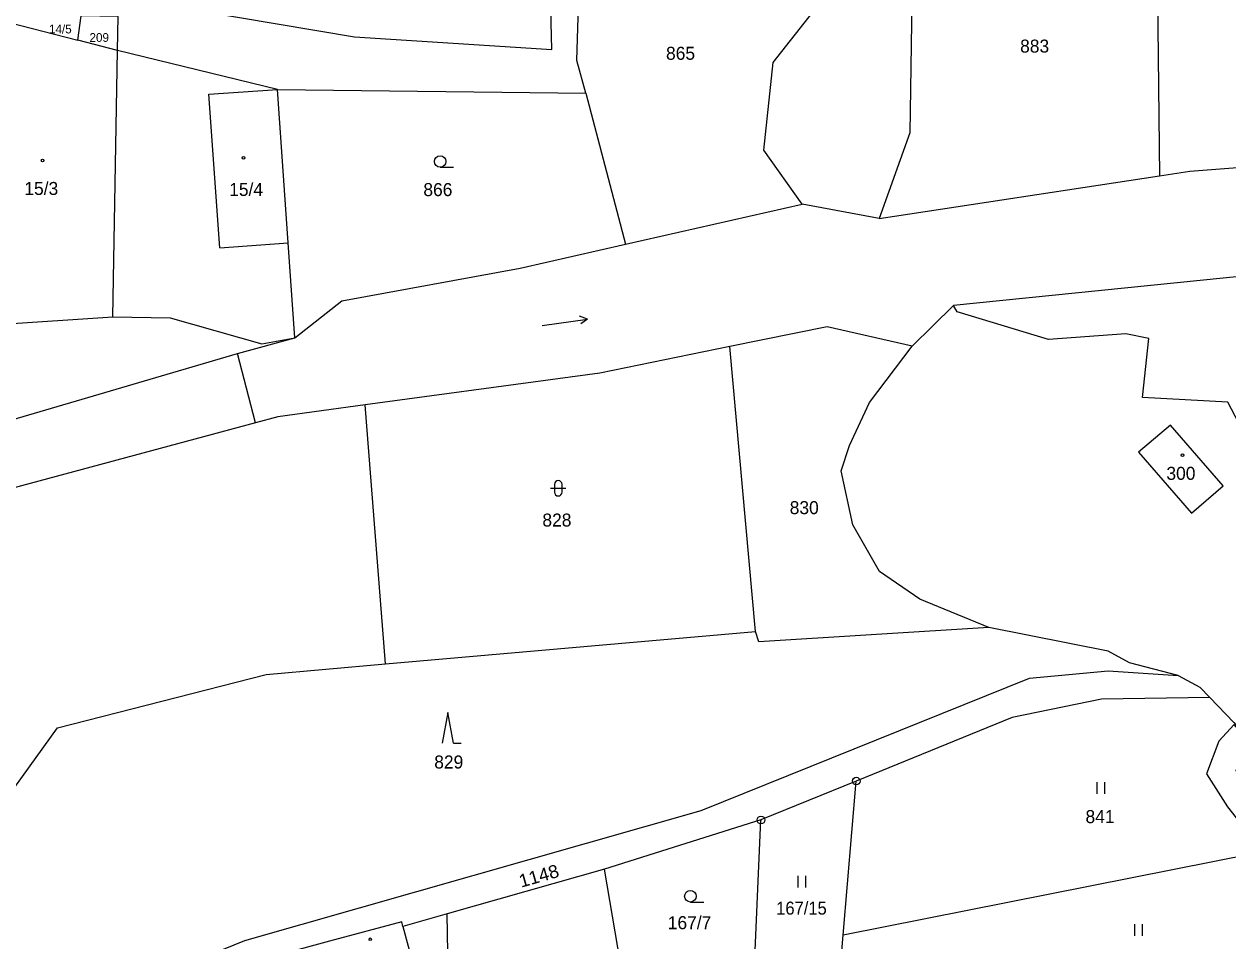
# Model space of a CAD drawing. Extents: x -758887 to -754328, y -1031688 to -1029144.
# Drawn here: x -756179.9 to -756022.6, y -1030418.1 to -1030298.3 of the extents above; entities that cross this region are included whole.
import ezdxf
from ezdxf.enums import TextEntityAlignment as Align

# ---------------------------------------------------------------- set-up
doc = ezdxf.new("R2010")
doc.units = 0
doc.header["$LTSCALE"] = 0.68
for name, color, linetype, lineweight in [('1', 7, 'Continuous', 25), ('13', 7, 'Continuous', 13), ('3', 7, 'Continuous', 25), ('4', 7, 'Continuous', 13), ('5', 7, 'Continuous', 25), ('8', 7, 'Continuous', 25)]:
    doc.layers.add(name, color=color, linetype=linetype, lineweight=lineweight)
doc.layers.add('2', color=7, linetype='Continuous')

msp = doc.modelspace()

# ---------------------------------------------------------------- linework, layer by layer
at = {"layer": '1'}
for p, q in [((-756031.94, -1030281.2), (-756031.56, -1030318.15)), ((-756186.43, -1030296.97), (-756172.86, -1030300.43)), ((-756172.86, -1030300.43), (-756172.41, -1030297.26)), ((-756167.68, -1030301.76), (-756172.86, -1030300.43)), ((-756168.3, -1030336.57), (-756167.68, -1030301.76)), ((-756146.76, -1030306.87), (-756106.51, -1030307.37)), ((-756068.18, -1030323.72), (-756078.24, -1030321.83)), ((-756058.47, -1030335.08), (-756063.85, -1030340.41)), ((-756187.15, -1030337.79), (-756168.3, -1030336.57)), ((-756152, -1030341.34), (-756144.51, -1030339.31)), ((-756149.65, -1030350.41), (-756152, -1030341.34)), ((-756008.68, -1030404.59), (-756072.87, -1030417.3))]:
    msp.add_line(p, q, dxfattribs=at)
for points in [[(-756171.95, -1030294.02), (-756136.72, -1030299.99), (-756110.94, -1030301.63), (-756111.35, -1030284.16), (-756108.96, -1030258.41)], [(-756106.51, -1030307.37), (-756107.65, -1030303.07), (-756106.9, -1030277.64), (-756074.7, -1030279.17)], [(-756031.56, -1030318.15), (-756027.6, -1030317.55), (-755993.58, -1030314.94), (-755968.82, -1030314.78), (-755939.82, -1030317.52), (-755926.81, -1030318.87), (-755868.93, -1030277.47)], [(-756078.24, -1030321.83), (-756083.22, -1030314.81), (-756082.01, -1030303.33), (-756076.85, -1030296.77), (-756074.7, -1030279.17)], [(-756063.12, -1030279.72), (-756063.67, -1030280.99), (-756064.16, -1030312.53), (-756068.18, -1030323.72), (-756031.56, -1030318.15)], [(-756167.68, -1030301.76), (-756167.6, -1030297.36), (-756172.41, -1030297.26)], [(-756144.51, -1030339.31), (-756145.37, -1030326.92), (-756146.76, -1030306.87), (-756167.68, -1030301.76)], [(-756106.51, -1030307.37), (-756101.3, -1030327.07), (-756078.24, -1030321.83)], [(-756144.51, -1030339.31), (-756138.35, -1030334.47), (-756115.05, -1030330.2), (-756101.3, -1030327.07)], [(-756000.08, -1030329.2), (-756019.79, -1030331.15), (-756058.47, -1030335.08)], [(-756007.39, -1030376.79), (-756022.62, -1030347.72), (-756033.77, -1030347.09), (-756032.93, -1030339.38), (-756035.95, -1030338.8), (-756046.04, -1030339.54), (-756058, -1030335.9), (-756058.47, -1030335.08)], [(-756168.3, -1030336.57), (-756160.8, -1030336.7), (-756148.82, -1030340.11), (-756144.51, -1030339.31)], [(-756063.85, -1030340.41), (-756074.95, -1030337.86), (-756087.68, -1030340.45)], [(-756087.68, -1030340.45), (-756104.68, -1030343.91), (-756135.32, -1030348.08)], [(-756132.67, -1030381.9), (-756084.32, -1030377.68), (-756087.68, -1030340.45)], [(-756053.85, -1030377.12), (-756062.84, -1030373.43), (-756068.14, -1030369.83), (-756071.62, -1030363.71), (-756073.15, -1030356.66), (-756072.04, -1030353.35), (-756069.43, -1030347.75), (-756063.85, -1030340.41)], [(-756257.6, -1030369.08), (-756250.83, -1030368.82), (-756245.31, -1030366.48), (-756219.4, -1030360.24), (-756181.47, -1030350.02), (-756152, -1030341.34)], [(-756183.93, -1030401.88), (-756175.52, -1030390.23), (-756148.24, -1030383.26), (-756132.67, -1030381.9), (-756135.32, -1030348.08)], [(-756135.32, -1030348.08), (-756146.73, -1030349.63), (-756149.65, -1030350.41)], [(-756149.65, -1030350.41), (-756190.47, -1030361.36), (-756242.58, -1030375.6), (-756250.11, -1030374.41), (-756256.28, -1030374.07)], [(-756053.85, -1030377.12), (-756083.89, -1030378.99), (-756084.32, -1030377.68)], [(-756029.12, -1030383.41), (-756035.45, -1030381.77), (-756038.25, -1030380.24), (-756053.85, -1030377.12)], [(-756177.1, -1030432.5), (-756161.02, -1030422.06), (-756151.02, -1030418.01), (-756091.41, -1030401.05), (-756048.53, -1030383.75), (-756038.26, -1030382.8), (-756029.12, -1030383.41)], [(-756029.12, -1030383.41), (-756026.26, -1030384.94), (-756024.98, -1030386.27)], [(-756024.98, -1030386.27), (-756039.14, -1030386.49), (-756050.8, -1030388.89), (-756071.16, -1030397.2)], [(-756024.98, -1030386.27), (-756021.83, -1030389.54), (-756008.68, -1030404.59)], [(-756084.22, -1030434.94), (-756074.39, -1030435.22), (-756073.62, -1030426.17), (-756072.87, -1030417.3), (-756071.16, -1030397.2), (-756083.61, -1030402.28)], [(-756084.58, -1030424.35), (-756083.61, -1030402.28), (-756104.05, -1030408.71)], [(-756099.56, -1030435.05), (-756104.05, -1030408.71), (-756124.62, -1030414.55)], [(-756159.24, -1030426.06), (-756141.08, -1030427.61), (-756124.32, -1030432.31), (-756124.62, -1030414.55)], [(-756124.62, -1030414.55), (-756130.39, -1030416.19), (-756130.55, -1030415.6), (-756139.97, -1030418.11), (-756144.28, -1030419.26), (-756145.41, -1030419.56), (-756145.19, -1030420.4), (-756146.46, -1030420.76), (-756159.24, -1030426.06)]]:
    msp.add_lwpolyline(points, dxfattribs=at)
msp.add_lwpolyline([(-756030.1, -1030350.71), (-756034.29, -1030354.23), (-756027.37, -1030362.2), (-756023.21, -1030358.63)], close=True, dxfattribs=at)
at = {"layer": '13'}
msp.add_lwpolyline([(-756019.47, -1030392.45), (-756021.8, -1030389.82), (-756023.81, -1030391.98), (-756025.42, -1030396.23), (-756022.67, -1030400.56), (-756018.12, -1030406.3), (-756017.97, -1030406.43), (-756013.61, -1030405.57), (-756015.58, -1030403.86), (-756019.81, -1030398.52), (-756021.52, -1030395.83), (-756020.96, -1030394.34), (-756019.78, -1030392.78)], close=True, dxfattribs=at)
at = {"layer": '3'}
for p, q in [((-756125.513, -1030317.03), (-756123.763, -1030317.03)), ((-756106.261, -1030336.849), (-756107.159, -1030337.481)), ((-756111.101, -1030358.961), (-756109.099, -1030358.961)), ((-756110.601, -1030358.461), (-756110.601, -1030359.462)), ((-756109.599, -1030359.462), (-756109.599, -1030358.461)), ((-756123.78, -1030392.26), (-756122.784, -1030392.26)), ((-756039.691, -1030398.85), (-756039.691, -1030397.35)), ((-756038.69, -1030398.85), (-756038.69, -1030397.35)), ((-756078.731, -1030411.09), (-756078.731, -1030409.59)), ((-756077.73, -1030411.09), (-756077.73, -1030409.59)), ((-756092.833, -1030412.99), (-756091.083, -1030412.99)), ((-756034.781, -1030417.4), (-756034.781, -1030415.9)), ((-756033.78, -1030417.4), (-756033.78, -1030415.9))]:
    msp.add_line(p, q, dxfattribs=at)
for points in [[(-756112.203, -1030337.684), (-756106.261, -1030336.849), (-756107.298, -1030336.488)], [(-756123.78, -1030392.26), (-756124.53, -1030388.26), (-756125.28, -1030392.26)]]:
    msp.add_lwpolyline(points, dxfattribs=at)
for centre in [(-756125.5129, -1030316.2798), (-756092.8329, -1030412.2398)]:
    msp.add_circle(centre, 0.75, dxfattribs=at)
for centre, start, end in [((-756110.1, -1030358.4609), 0, 180), ((-756110.1, -1030359.4609), 180, 359.98789)]:
    msp.add_arc(centre, 0.5, start, end, dxfattribs=at)
at = {"layer": '4'}
for p, q in [((-756155.73, -1030307.5), (-756146.76, -1030306.87)), ((-756154.32, -1030327.55), (-756155.73, -1030307.5)), ((-756154.32, -1030327.55), (-756145.37, -1030326.92)), ((-756130.39, -1030416.19), (-756129.02, -1030421.33))]:
    msp.add_line(p, q, dxfattribs=at)
at = {"layer": '5'}
for centre in [(-756151.2268, -1030315.7992), (-756177.4568, -1030316.1492), (-756028.5368, -1030354.6292), (-756134.6468, -1030417.8592)]:
    msp.add_circle(centre, 0.175, dxfattribs=at)
at = {"layer": '8'}
for centre, radius in [((-756071.16, -1030397.1999), 0.5), ((-756071.16, -1030397.1999), 0.0303), ((-756083.61, -1030402.2799), 0.5), ((-756083.61, -1030402.2799), 0.0303)]:
    msp.add_circle(centre, radius, dxfattribs=at)

# ---------------------------------------------------------------- texts
at = {"layer": '2'}
for s, height, p in [('14/5', 1.14, (-756175.139, -1030299.55)), ('209', 1.14, (-756170.06, -1030300.65)), ('865', 1.7, (-756094.119, -1030302.996)), ('883', 1.7, (-756047.859, -1030302.056)), ('15/3', 1.7, (-756177.63, -1030320.65)), ('15/4', 1.7, (-756150.87, -1030320.78)), ('866', 1.7, (-756125.819, -1030320.796)), ('300', 1.7, (-756028.749, -1030357.856)), ('830', 1.7, (-756077.959, -1030362.336)), ('828', 1.7, (-756110.269, -1030363.956)), ('829', 1.7, (-756124.399, -1030395.556)), ('841', 1.7, (-756039.319, -1030402.686)), ('167/7', 1.7, (-756092.94, -1030416.54))]:
    msp.add_text(s, height=height, dxfattribs=at).set_placement(p, align=Align.CENTER)
at = {"layer": '2', "width": 1.05}
msp.add_text('1148', height=1.7, rotation=16, dxfattribs=at).set_placement((-756112.3923, -1030410.396), align=Align.CENTER)
at = {"layer": '2', "width": 0.95}
msp.add_text('167/15', height=1.7, dxfattribs=at).set_placement((-756078.319, -1030414.64), align=Align.CENTER)

doc.saveas('drawing.dxf')
